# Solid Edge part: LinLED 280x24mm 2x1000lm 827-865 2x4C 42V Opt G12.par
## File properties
Author: robert.pupel
Template: iso metric part.par
Last saved by: robert.pupel
Revision: 1
Application: Solid Edge
Gęstość: 0.000 kg/m^3
Dokładność: 0.990
Username: robert.pupel
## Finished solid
Body 1: solid body, 2820 faces, 7196 edges, 4528 vertices.
  Faces by surface: plane 1663, cylinder 517, spline 384, cone 120, sphere 64, torus 40, spun 32
  Edges by curve: line 4738, curve on surface 1296, circle 682, ellipse 264, spline 200, intersection 16
Bounding box of the edges (mm; curved faces can reach further): 279.500 x 4.450 x 24.000, from (-139.75, -4.45, -12) to (139.75, 0, 12).
Cylindrical faces by radius (mm): R0.2 x184, R0.2169 x24, R0.25 x56, R0.3373 x24, R0.4 x32, R0.4006 x8, R0.4008 x8, R0.525 x8, R0.6 x80, R1 x32, R1.1 x16, R1.2 x40, R2.15 x5
Conical faces (half-angle, radius in mm at the cone's reference point): 0.5 deg R0.5056 x16, 0.5 deg R1.0082 x16, 1 deg R0.5511 x8, 10 deg R0.2132 x16, 10 deg R0.4132 x16, 18.8604 deg R1.0669 x16, 27.363 deg R0.6214 x8, 45 deg R0.575 x8, 45 deg R0.625 x16
Toroidal faces (ring radius, tube radius in mm): R0.8 r0.2 x16, R0.8522 r0.3 x8, R0.9002 r0.2 x8, R0.9018 r0.2 x8
Spherical faces by radius (mm): R0.2 x48, R0.6 x16
Planar faces by outward normal: +x 176, +y 33, +z 180, -x 176, -y 265, -z 181, oblique 652
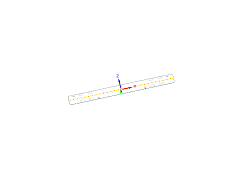
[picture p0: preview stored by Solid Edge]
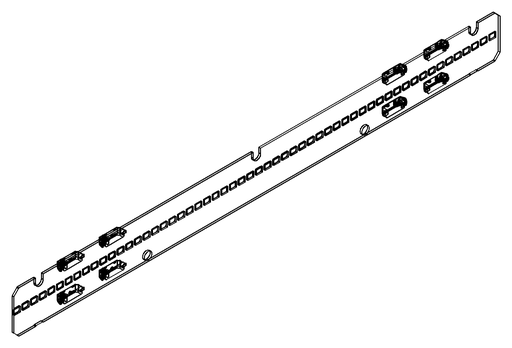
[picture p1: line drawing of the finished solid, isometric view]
